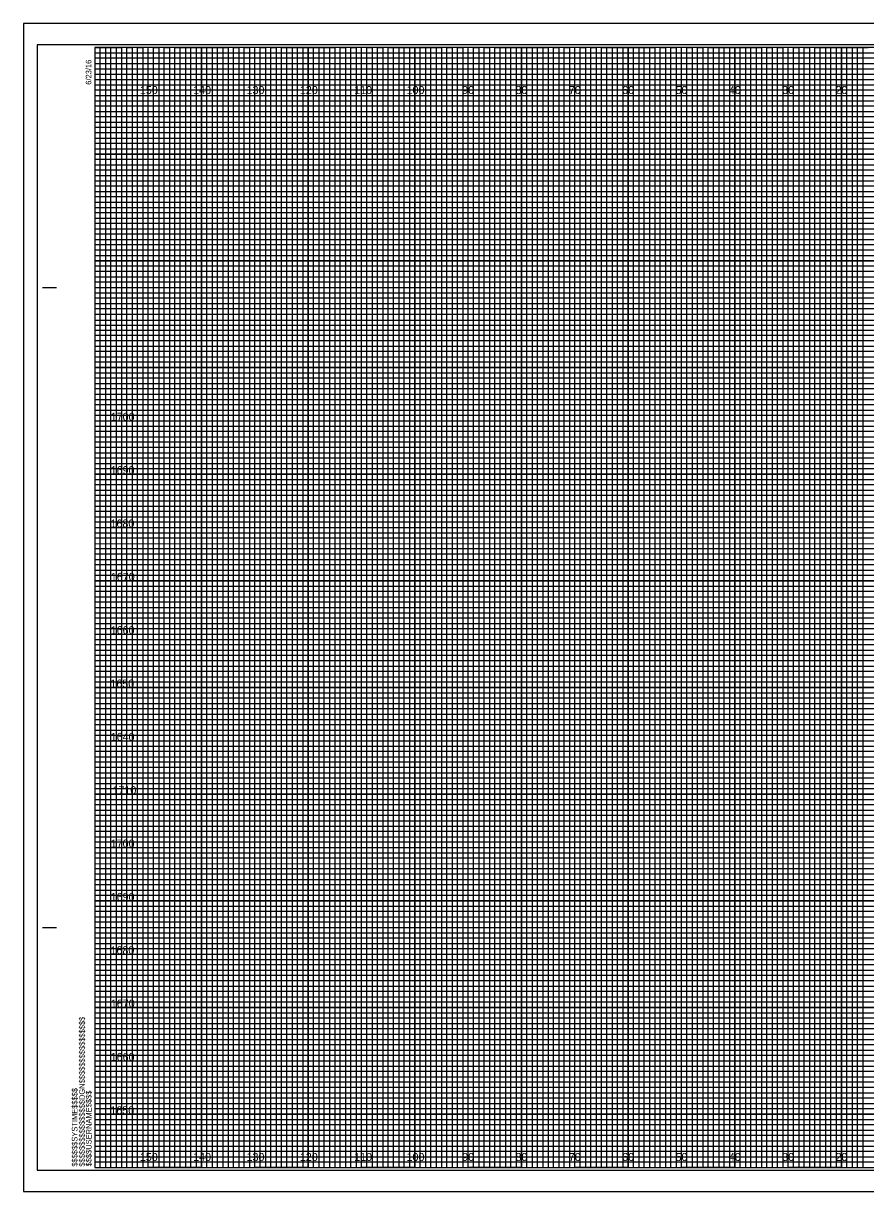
# Model space of a CAD drawing. Extents: x 656 to 993, y -2 to 2857.
# Drawn here: x 656.3 to 814.2, y 658.3 to 877.3 of the extents above; entities that cross this region are included whole.
import ezdxf

# ---------------------------------------------------------------- set-up
doc = ezdxf.new("R2010")
doc.units = 0
for name, color, linetype in [('Prop RDY Alternate Text Blue', 7, 'Continuous'), ('Prop Retaining Wall', 7, 'Continuous'), ('Prop SS Cut Line', 7, 'Continuous'), ('Prop SS Fill Line', 7, 'Continuous'), ('Prop SS Transition Line', 7, 'Continuous'), ('Raster_Level_0', 7, 'Continuous'), ('Raster_Level_3', 7, 'Continuous'), ('Scratch_Level_3', 7, 'Continuous'), ('Scratch_Level_7', 7, 'Continuous'), ('Typical Guardrail CELL', 7, 'Continuous'), ('Typical Text Asphalt at Bridge Approach CELL', 7, 'Continuous')]:
    doc.layers.add(name, color=color, linetype=linetype)

msp = doc.modelspace()

# ---------------------------------------------------------------- linework, layer by layer
at = {"layer": 'Prop RDY Alternate Text Blue'}
for p, q in [((679.74, 662.8), (679.74, 872.8)), ((689.74, 662.8), (689.74, 872.8)), ((699.74, 662.8), (699.74, 872.8)), ((709.74, 662.8), (709.74, 872.8)), ((719.74, 662.8), (719.74, 872.8)), ((729.74, 662.8), (729.74, 872.8)), ((739.74, 662.8), (739.74, 872.8)), ((749.74, 662.8), (749.74, 872.8)), ((759.74, 662.8), (759.74, 872.8)), ((769.74, 662.8), (769.74, 872.8)), ((779.74, 662.8), (779.74, 872.8)), ((789.74, 662.8), (789.74, 872.8)), ((799.74, 662.8), (799.74, 872.8)), ((809.74, 662.8), (809.74, 872.8)), ((669.74, 862.8), (989.74, 862.8)), ((669.74, 852.8), (989.74, 852.8)), ((669.74, 842.8), (989.74, 842.8)), ((669.74, 832.8), (989.74, 832.8)), ((669.74, 822.8), (989.74, 822.8)), ((669.74, 812.8), (989.74, 812.8)), ((669.74, 802.8), (989.74, 802.8)), ((669.74, 792.8), (989.74, 792.8)), ((669.74, 782.8), (989.74, 782.8)), ((669.74, 772.8), (989.74, 772.8)), ((669.74, 762.8), (989.74, 762.8)), ((669.74, 752.8), (989.74, 752.8)), ((669.74, 742.8), (989.74, 742.8)), ((669.74, 732.8), (989.74, 732.8)), ((669.74, 722.8), (989.74, 722.8)), ((669.74, 712.8), (989.74, 712.8)), ((669.74, 702.8), (989.74, 702.8)), ((669.74, 692.8), (989.74, 692.8)), ((669.74, 682.8), (989.74, 682.8)), ((669.74, 672.8), (989.74, 672.8))]:
    msp.add_line(p, q, dxfattribs=at)
at = {"layer": 'Prop Retaining Wall'}
for p, q in [((659.94, 827.8), (662.44, 827.8)), ((660.04, 827.8), (662.54, 827.8)), ((659.94, 707.8), (662.44, 707.8)), ((660.04, 707.8), (662.54, 707.8)), ((669.74, 662.8), (669.74, 662.8)), ((669.74, 662.8), (669.74, 662.8)), ((669.74, 662.8), (669.74, 662.8)), ((669.74, 662.8), (669.74, 662.8)), ((669.74, 662.8), (669.74, 662.8)), ((669.74, 662.8), (669.74, 662.8)), ((669.74, 662.8), (669.74, 662.8))]:
    msp.add_line(p, q, dxfattribs=at)
msp.add_lwpolyline([(989.74, 872.8), (669.74, 872.8), (669.74, 662.8), (989.74, 662.8)], close=True, dxfattribs=at)
at = {"layer": 'Prop SS Cut Line'}
for points in [[(669.74, 872.8), (674.74, 872.8), (674.74, 662.8), (684.74, 662.8), (684.74, 872.8), (694.74, 872.8), (694.74, 662.8), (704.74, 662.8), (704.74, 872.8), (714.74, 872.8), (714.74, 662.8), (724.74, 662.8), (724.74, 872.8), (734.74, 872.8), (734.74, 662.8), (744.74, 662.8), (744.74, 872.8), (754.74, 872.8), (754.74, 662.8), (764.74, 662.8), (764.74, 872.8), (774.74, 872.8), (774.74, 662.8), (784.74, 662.8), (784.74, 872.8), (794.74, 872.8), (794.74, 662.8), (804.74, 662.8), (804.74, 872.8), (814.74, 872.8)], [(669.74, 867.8), (944.74, 867.8)], [(669.74, 847.8), (989.74, 847.8), (989.74, 857.8), (669.74, 857.8)], [(669.74, 827.8), (989.74, 827.8), (989.74, 837.8), (669.74, 837.8)], [(669.74, 807.8), (989.74, 807.8), (989.74, 817.8), (669.74, 817.8)], [(669.74, 787.8), (989.74, 787.8), (989.74, 797.8), (669.74, 797.8)], [(669.74, 767.8), (989.74, 767.8), (989.74, 777.8), (669.74, 777.8)], [(669.74, 747.8), (989.74, 747.8), (989.74, 757.8), (669.74, 757.8)], [(669.74, 727.8), (989.74, 727.8), (989.74, 737.8), (669.74, 737.8)], [(669.74, 707.8), (989.74, 707.8), (989.74, 717.8), (669.74, 717.8)], [(669.74, 687.8), (989.74, 687.8), (989.74, 697.8), (669.74, 697.8)], [(669.74, 667.8), (989.74, 667.8), (989.74, 677.8), (669.74, 677.8)]]:
    msp.add_lwpolyline(points, dxfattribs=at)
at = {"layer": 'Prop SS Fill Line'}
for p, q in [((679.74, 872.8), (669.74, 872.8)), ((679.74, 662.8), (679.74, 872.8)), ((699.74, 872.8), (689.74, 872.8)), ((689.74, 872.8), (689.74, 662.8)), ((699.74, 662.8), (699.74, 872.8)), ((719.74, 872.8), (709.74, 872.8)), ((709.74, 872.8), (709.74, 662.8)), ((719.74, 662.8), (719.74, 872.8)), ((739.74, 872.8), (729.74, 872.8)), ((729.74, 872.8), (729.74, 662.8)), ((739.74, 662.8), (739.74, 872.8)), ((759.74, 872.8), (749.74, 872.8)), ((749.74, 872.8), (749.74, 662.8)), ((759.74, 662.8), (759.74, 872.8)), ((779.74, 872.8), (769.74, 872.8)), ((769.74, 872.8), (769.74, 662.8)), ((779.74, 662.8), (779.74, 872.8)), ((799.74, 872.8), (789.74, 872.8)), ((789.74, 872.8), (789.74, 662.8)), ((799.74, 662.8), (799.74, 872.8)), ((819.74, 872.8), (809.74, 872.8)), ((809.74, 872.8), (809.74, 662.8)), ((689.74, 662.8), (679.74, 662.8)), ((709.74, 662.8), (699.74, 662.8)), ((729.74, 662.8), (719.74, 662.8)), ((749.74, 662.8), (739.74, 662.8)), ((769.74, 662.8), (759.74, 662.8)), ((789.74, 662.8), (779.74, 662.8)), ((809.74, 662.8), (799.74, 662.8))]:
    msp.add_line(p, q, dxfattribs=at)
for points in [[(669.74, 862.8), (989.74, 862.8), (989.74, 852.8), (669.74, 852.8)], [(669.74, 842.8), (989.74, 842.8), (989.74, 832.8), (669.74, 832.8)], [(669.74, 822.8), (989.74, 822.8), (989.74, 812.8), (669.74, 812.8)], [(669.74, 802.8), (989.74, 802.8), (989.74, 792.8), (669.74, 792.8)], [(669.74, 782.8), (989.74, 782.8), (989.74, 772.8), (669.74, 772.8)], [(669.74, 762.8), (989.74, 762.8), (989.74, 752.8), (669.74, 752.8)], [(669.74, 742.8), (989.74, 742.8), (989.74, 732.8), (669.74, 732.8)], [(669.74, 722.8), (989.74, 722.8), (989.74, 712.8), (669.74, 712.8)], [(669.74, 702.8), (989.74, 702.8), (989.74, 692.8), (669.74, 692.8)], [(669.74, 682.8), (989.74, 682.8), (989.74, 672.8), (669.74, 672.8)]]:
    msp.add_lwpolyline(points, dxfattribs=at)
at = {"layer": 'Prop SS Transition Line'}
for p, q in [((669.74, 871.8), (929.74, 871.8)), ((929.74, 870.78), (669.74, 870.78)), ((669.74, 870.78), (669.74, 869.8)), ((669.74, 869.8), (929.74, 869.8)), ((929.74, 868.69), (669.74, 868.69)), ((669.74, 868.69), (669.74, 866.8)), ((669.74, 866.8), (989.74, 866.8))]:
    msp.add_line(p, q, dxfattribs=at)
for points in [[(669.74, 865.8), (939.74, 865.8), (989.74, 865.8), (989.74, 864.8), (669.74, 864.8)], [(669.74, 863.8), (989.74, 863.8), (989.74, 861.8), (669.74, 861.8)], [(669.74, 860.8), (989.74, 860.8), (989.74, 859.8), (669.74, 859.78)], [(669.74, 858.8), (989.74, 858.8), (989.74, 856.8), (669.74, 856.8)], [(669.74, 855.8), (989.74, 855.8), (989.74, 854.8), (669.74, 854.8)], [(669.74, 853.8), (989.74, 853.8), (989.74, 851.8), (669.74, 851.8)], [(669.74, 850.8), (989.74, 850.8), (989.74, 849.8), (669.74, 849.8)], [(669.74, 848.8), (989.74, 848.8), (989.74, 846.8), (669.74, 846.8)], [(669.74, 845.8), (989.74, 845.8), (989.74, 844.8), (669.74, 844.8)], [(669.74, 843.8), (989.74, 843.8), (989.74, 841.8), (669.74, 841.8)], [(669.74, 840.8), (989.74, 840.8), (989.74, 839.8), (669.74, 839.8)], [(669.74, 838.8), (989.74, 838.8), (989.74, 836.75), (989.74, 835.8), (989.74, 834.8), (669.74, 834.8)], [(669.74, 836.8), (989.74, 836.8), (989.74, 835.8), (669.74, 835.8)], [(669.74, 833.8), (989.74, 833.8), (989.74, 831.8), (669.74, 831.83)], [(669.74, 831.83), (989.74, 831.8), (989.74, 830.8), (669.74, 830.8)], [(669.74, 829.8), (989.74, 829.8), (989.74, 828.8), (669.74, 828.8)], [(669.74, 826.8), (989.74, 826.8), (989.74, 825.8), (669.74, 825.8)], [(669.74, 824.8), (989.74, 824.8), (989.74, 823.8), (669.74, 823.8)], [(669.67, 821.69), (989.74, 821.69), (989.74, 820.68), (669.67, 820.68)], [(669.74, 819.8), (989.74, 819.8), (989.74, 818.8), (669.74, 818.8)], [(669.74, 816.8), (989.74, 816.8), (989.74, 815.8), (669.74, 815.8)], [(669.74, 814.8), (989.74, 814.8), (989.74, 813.8), (669.74, 813.8)], [(669.74, 811.8), (989.74, 811.8), (989.74, 810.8), (669.74, 810.8)], [(669.74, 809.8), (989.74, 809.8), (989.74, 808.8), (669.74, 808.8)], [(669.74, 806.8), (989.74, 806.8), (989.74, 805.8), (669.74, 805.8)], [(669.74, 804.8), (989.74, 804.8), (989.74, 803.8), (669.74, 803.8)], [(669.74, 801.8), (989.74, 801.8), (989.73, 800.78), (669.74, 800.8)], [(669.74, 799.8), (989.74, 799.8), (989.74, 798.8), (669.74, 798.8)], [(669.74, 796.8), (989.74, 796.8), (989.74, 795.8), (669.74, 795.8)], [(669.74, 794.8), (989.74, 794.8), (989.74, 793.8), (669.74, 793.8)], [(669.74, 791.8), (989.74, 791.8), (989.74, 790.8), (669.74, 790.8)], [(669.74, 789.8), (989.74, 789.8), (989.74, 788.8), (669.74, 788.8)], [(669.74, 786.8), (989.74, 786.8), (989.74, 785.8), (669.74, 785.8)], [(669.74, 784.8), (989.74, 784.8), (989.74, 783.8), (669.74, 783.8)], [(669.74, 781.8), (989.74, 781.8), (989.74, 780.8), (669.74, 780.8)], [(669.74, 779.79), (989.81, 779.71), (989.74, 778.8), (669.74, 778.8)], [(669.74, 776.8), (989.74, 776.8), (989.74, 775.8), (669.74, 775.8)], [(669.74, 774.8), (989.74, 774.8), (989.74, 773.8), (669.74, 773.8)], [(669.74, 771.8), (989.74, 771.8), (989.74, 770.8), (669.74, 770.8)], [(669.74, 769.8), (989.74, 769.8), (989.74, 768.8), (669.74, 768.8)], [(669.74, 766.8), (989.74, 766.8), (989.74, 765.8), (669.74, 765.8)], [(669.74, 764.8), (989.74, 764.8), (989.74, 763.8), (669.74, 763.8)], [(669.74, 761.8), (989.74, 761.8), (989.74, 760.8), (669.74, 760.8)], [(669.74, 759.8), (989.74, 759.8), (989.74, 758.8), (669.74, 758.8)], [(669.74, 756.8), (989.74, 756.8), (989.74, 755.8), (669.74, 755.8)], [(669.74, 754.8), (989.74, 754.8), (989.74, 753.8), (669.74, 753.8)], [(669.74, 751.8), (989.74, 751.8), (989.74, 750.8), (669.74, 750.8)], [(669.74, 749.8), (989.74, 749.8), (989.74, 748.8), (669.74, 748.8)], [(669.74, 746.8), (989.74, 746.8), (989.74, 745.8), (669.74, 745.8)], [(669.74, 744.8), (989.74, 744.8), (989.74, 743.8), (669.74, 743.8)], [(669.74, 741.8), (989.74, 741.8), (989.73, 740.78), (669.74, 740.8)], [(669.74, 739.8), (989.74, 739.8), (989.74, 738.8), (669.74, 738.8)], [(669.74, 736.8), (989.74, 736.8), (989.74, 735.8), (669.74, 735.8)], [(669.74, 734.8), (989.74, 734.8), (989.74, 733.8), (669.74, 733.8)], [(669.74, 731.8), (989.74, 731.8), (989.74, 730.8), (669.74, 730.8)], [(669.74, 729.8), (989.74, 729.8), (989.74, 728.8), (669.74, 728.8)], [(669.74, 726.8), (989.74, 726.8), (989.74, 725.8), (669.74, 725.8)], [(669.74, 724.8), (989.74, 724.8), (989.74, 723.8), (669.74, 723.8)], [(669.74, 721.8), (989.74, 721.8), (989.74, 720.8), (669.74, 720.8)], [(669.74, 719.79), (989.81, 719.71), (989.74, 718.8), (669.74, 718.8)], [(669.74, 716.8), (989.74, 716.8), (989.74, 715.8), (669.74, 715.8)], [(669.74, 714.8), (989.74, 714.8), (989.74, 713.8), (669.74, 713.8)], [(669.74, 711.8), (989.74, 711.8), (989.74, 710.8), (669.74, 710.8)], [(669.74, 709.8), (989.74, 709.8), (989.74, 708.8), (669.74, 708.8)], [(669.74, 706.8), (989.74, 706.8), (989.74, 705.8), (669.74, 705.8)], [(669.74, 704.8), (989.74, 704.8), (989.74, 703.8), (669.74, 703.8)], [(669.74, 701.8), (989.74, 701.8), (989.74, 700.8), (669.74, 700.8)], [(669.74, 699.8), (989.74, 699.8), (989.74, 698.8), (669.74, 698.8)], [(669.74, 696.8), (989.74, 696.8), (989.74, 695.8), (669.74, 695.8)], [(669.74, 694.8), (989.74, 694.8), (989.74, 693.8), (669.74, 693.8)], [(669.74, 691.8), (989.74, 691.8), (989.74, 690.8), (669.74, 690.8)], [(669.74, 689.8), (989.74, 689.8), (989.74, 688.8), (669.74, 688.8)], [(669.74, 686.8), (989.74, 686.8), (989.74, 685.8), (669.74, 685.8)], [(669.74, 684.8), (989.74, 684.8), (989.74, 683.8), (669.74, 683.8)], [(669.74, 681.8), (989.74, 681.8), (989.74, 680.8), (669.74, 680.8)], [(669.74, 679.8), (989.74, 679.8), (989.74, 678.8), (669.74, 678.8)], [(669.74, 676.8), (989.74, 676.8), (989.74, 675.8), (669.74, 675.8)], [(669.74, 674.8), (989.74, 674.8), (989.74, 673.8), (669.74, 673.8)], [(669.74, 671.8), (989.74, 671.8), (989.74, 670.8), (669.74, 670.8)], [(669.74, 669.8), (989.74, 669.8), (989.74, 668.8), (669.74, 668.8)], [(669.74, 666.8), (989.74, 666.8), (989.74, 665.8), (669.74, 665.8)], [(669.74, 664.8), (989.74, 664.8), (989.74, 663.8), (669.74, 663.8)]]:
    msp.add_lwpolyline(points, dxfattribs=at)
at = {"layer": 'Raster_Level_3'}
for points in [[(669.74, 662.8), (670.74, 662.8), (670.74, 872.8), (671.74, 872.8), (671.74, 662.8)], [(671.74, 662.8), (672.74, 662.8), (672.74, 872.8), (673.74, 872.8), (673.74, 662.8)], [(674.74, 662.8), (675.74, 662.8), (675.74, 872.8), (676.74, 872.8), (676.74, 662.8)], [(676.74, 662.8), (677.74, 662.8), (677.74, 872.8), (678.74, 872.8), (678.74, 662.8)], [(679.74, 662.8), (680.74, 662.8), (680.74, 872.8), (681.74, 872.8), (681.74, 662.8)], [(681.74, 662.8), (682.74, 662.8), (682.74, 872.8), (683.74, 872.8), (683.74, 662.8)], [(684.74, 662.8), (685.74, 662.8), (685.74, 872.8), (686.74, 872.8), (686.74, 662.8)], [(686.74, 662.8), (687.74, 662.8), (687.74, 872.8), (688.74, 872.8), (688.74, 662.8)], [(689.74, 662.8), (690.74, 662.8), (690.74, 872.8), (691.74, 872.8), (691.74, 662.8)], [(691.74, 662.8), (692.74, 662.8), (692.74, 872.8), (693.74, 872.8), (693.74, 662.8)], [(694.74, 662.8), (695.74, 662.8), (695.74, 872.8), (696.74, 872.8), (696.74, 662.8)], [(696.74, 662.8), (697.74, 662.8), (697.74, 872.8), (698.74, 872.8), (698.74, 662.8)], [(699.74, 662.8), (700.74, 662.8), (700.74, 872.8), (701.74, 872.8), (701.74, 662.8)], [(701.74, 662.8), (702.74, 662.8), (702.74, 872.8), (703.74, 872.8), (703.74, 662.8)], [(704.74, 662.8), (705.74, 662.8), (705.74, 872.8), (706.74, 872.8), (706.74, 662.8)], [(706.74, 662.8), (707.74, 662.8), (707.74, 872.8), (708.74, 872.8), (708.74, 662.8)], [(709.74, 662.8), (710.74, 662.8), (710.74, 872.8), (711.74, 872.8), (711.74, 662.8)], [(711.74, 662.8), (712.74, 662.8), (712.74, 872.8), (713.74, 872.8), (713.74, 662.8)], [(714.74, 662.8), (715.74, 662.8), (715.74, 872.8), (716.74, 872.8), (716.74, 662.8)], [(716.74, 662.8), (717.74, 662.8), (717.74, 872.8), (718.74, 872.8), (718.74, 662.8)], [(719.74, 662.8), (720.74, 662.8), (720.74, 872.8), (721.74, 872.8), (721.74, 662.8)], [(721.74, 662.8), (722.74, 662.8), (722.74, 872.8), (723.74, 872.8), (723.74, 662.8)], [(724.74, 662.8), (725.74, 662.8), (725.74, 872.8), (726.74, 872.8), (726.74, 662.8)], [(726.74, 662.8), (727.74, 662.8), (727.74, 872.8), (728.74, 872.8), (728.74, 662.8)], [(729.74, 662.8), (730.74, 662.8), (730.74, 872.8), (731.74, 872.8), (731.74, 662.8)], [(731.74, 662.8), (732.74, 662.8), (732.74, 872.8), (733.74, 872.8), (733.74, 662.8)], [(734.74, 662.8), (735.74, 662.8), (735.74, 872.8), (736.74, 872.8), (736.74, 662.8)], [(736.74, 662.8), (737.74, 662.8), (737.74, 872.8), (738.74, 872.8), (738.74, 662.8)], [(739.74, 662.8), (740.74, 662.8), (740.74, 872.8), (741.74, 872.8), (741.74, 662.8)], [(741.74, 662.8), (742.74, 662.8), (742.74, 872.8), (743.74, 872.8), (743.74, 662.8)], [(744.74, 662.8), (745.74, 662.8), (745.74, 872.8), (746.74, 872.8), (746.74, 662.8)], [(746.74, 662.8), (747.74, 662.8), (747.74, 872.8), (748.74, 872.8), (748.74, 662.8)], [(749.74, 662.8), (750.74, 662.8), (750.74, 872.8), (751.74, 872.8), (751.74, 662.8)], [(751.74, 662.8), (752.74, 662.8), (752.74, 872.8), (753.74, 872.8), (753.74, 662.8)], [(754.74, 662.8), (755.74, 662.8), (755.74, 872.8), (756.74, 872.8), (756.74, 662.8)], [(756.74, 662.8), (757.74, 662.8), (757.74, 872.8), (758.74, 872.8), (758.74, 662.8)], [(759.74, 662.8), (760.74, 662.8), (760.74, 872.8), (761.74, 872.8), (761.74, 662.8)], [(761.74, 662.8), (762.74, 662.8), (762.74, 872.8), (763.74, 872.8), (763.74, 662.8)], [(764.74, 662.8), (765.74, 662.8), (765.74, 872.8), (766.74, 872.8), (766.74, 662.8)], [(766.74, 662.8), (767.74, 662.8), (767.74, 872.8), (768.74, 872.8), (768.74, 662.8)], [(769.74, 662.8), (770.74, 662.8), (770.74, 872.8), (771.74, 872.8), (771.74, 662.8)], [(771.74, 662.8), (772.74, 662.8), (772.74, 872.8), (773.74, 872.8), (773.74, 662.8)], [(774.74, 662.8), (775.74, 662.8), (775.74, 872.8), (776.74, 872.8), (776.74, 662.8)], [(776.74, 662.8), (777.74, 662.8), (777.74, 872.8), (778.74, 872.8), (778.74, 662.8)], [(779.74, 662.8), (780.74, 662.8), (780.74, 872.8), (781.74, 872.8), (781.74, 662.8)], [(781.74, 662.8), (782.74, 662.8), (782.74, 872.8), (783.74, 872.8), (783.74, 662.8)], [(784.74, 662.8), (785.74, 662.8), (785.74, 872.8), (786.74, 872.8), (786.74, 662.8)], [(786.74, 662.8), (787.74, 662.8), (787.74, 872.8), (788.74, 872.8), (788.74, 662.8)], [(789.74, 662.8), (790.74, 662.8), (790.74, 872.8), (791.74, 872.8), (791.74, 662.8)], [(791.74, 662.8), (792.74, 662.8), (792.74, 872.8), (793.74, 872.8), (793.74, 662.8)], [(794.74, 662.8), (795.74, 662.8), (795.74, 872.8), (796.74, 872.8), (796.74, 662.8)], [(796.74, 662.8), (797.74, 662.8), (797.74, 872.8), (798.74, 872.8), (798.74, 662.8)], [(799.74, 662.8), (800.74, 662.8), (800.74, 872.8), (801.74, 872.8), (801.74, 662.8)], [(801.74, 662.8), (802.74, 662.8), (802.74, 872.8), (803.74, 872.8), (803.74, 662.8)], [(804.74, 662.8), (805.74, 662.8), (805.74, 872.8), (806.74, 872.8), (806.74, 662.8)], [(806.74, 662.8), (807.74, 662.8), (807.74, 872.8), (808.74, 872.8), (808.74, 662.8)], [(809.74, 662.8), (810.74, 662.8), (810.74, 872.8), (811.74, 872.8), (811.74, 662.8)], [(811.74, 662.8), (812.74, 662.8), (812.74, 872.8), (813.74, 872.8), (813.74, 662.8)]]:
    msp.add_lwpolyline(points, dxfattribs=at)
at = {"layer": 'Scratch_Level_7'}
msp.add_lwpolyline([(656.34, 658.3), (993.04, 658.3), (993.04, 877.3), (656.34, 877.3)], close=True, dxfattribs=at)
at = {"layer": 'Typical Guardrail CELL'}
msp.add_lwpolyline([(658.94, 662.3), (992.14, 662.3), (992.14, 873.3), (658.94, 873.3)], close=True, dxfattribs=at)
at = {"layer": 'Typical Text Asphalt at Bridge Approach CELL'}
for p, q in [((993.04, 877.3), (656.34, 877.3)), ((656.34, 877.3), (656.34, 658.3)), ((656.34, 658.3), (993.04, 658.3))]:
    msp.add_line(p, q, dxfattribs=at)

# ---------------------------------------------------------------- texts
at = {"layer": 'Prop Retaining Wall'}
for s, p in [('6/23/16', (669.09, 865.8)), ('$$$$$$$$$$$$$$$$DGN$$$$$$$$$$$$$$$$', (667.86, 662.98)), ('$$$$$$SYSTIME$$$$$', (666.48, 662.98)), ('$$$$USERNAME$$$$', (669.12, 663.03))]:
    msp.add_text(s, height=1.05, rotation=90, dxfattribs=at).set_placement(p)
at = {"layer": 'Raster_Level_0'}
for s, p in [('150', (678.18, 864.05)), ('140', (688.18, 864.05)), ('130', (698.18, 864.05)), ('120', (708.18, 864.05)), ('110', (718.36, 864.05)), ('100', (728.18, 864.05)), ('90', (738.6, 864.05)), ('80', (748.6, 864.05)), ('70', (758.6, 864.05)), ('60', (768.6, 864.05)), ('50', (778.6, 864.05)), ('40', (788.6, 864.05)), ('30', (798.6, 864.05)), ('20', (808.6, 864.05)), ('150', (678.18, 664.05)), ('140', (688.18, 664.05)), ('130', (698.18, 664.05)), ('120', (708.18, 664.05)), ('110', (718.36, 664.05)), ('100', (728.18, 664.05)), ('90', (738.6, 664.05)), ('80', (748.6, 664.05)), ('70', (758.6, 664.05)), ('60', (768.6, 664.05)), ('50', (778.6, 664.05)), ('40', (788.6, 664.05)), ('30', (798.6, 664.05)), ('20', (808.6, 664.05))]:
    msp.add_text(s, height=1.5, dxfattribs=at).set_placement(p)
at = {"layer": 'Scratch_Level_3'}
for s, p in [('1700', (672.72, 802.8)), ('1690', (672.71, 792.8)), ('1680', (672.68, 782.8)), ('1670', (672.74, 772.8)), ('1660', (672.71, 762.8)), ('1650', (672.66, 752.8)), ('1640', (672.71, 742.8)), ('1710', (673.05, 732.8)), ('1700', (672.72, 722.8)), ('1690', (672.71, 712.8)), ('1680', (672.68, 702.8)), ('1670', (672.74, 692.8)), ('1660', (672.71, 682.8)), ('1650', (672.66, 672.8))]:
    msp.add_text(s, height=1.5, dxfattribs=at).set_placement(p)

doc.saveas('drawing.dxf')
